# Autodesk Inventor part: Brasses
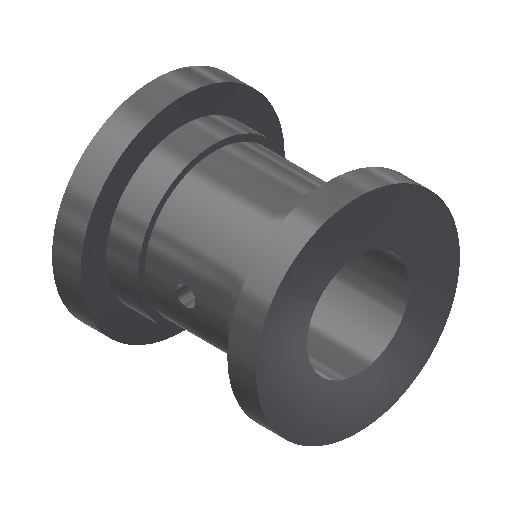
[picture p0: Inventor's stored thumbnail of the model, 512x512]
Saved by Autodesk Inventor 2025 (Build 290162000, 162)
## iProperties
Created: 2009-04
Part Number: Brasses
Document SubType Name: Modeling
Designer: Sham
Density: 7.85 g/cm^3
Material: Steel
Appearance: Smooth - Medium Gray
Author: Sham
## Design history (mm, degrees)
sketch "Sketch1"
  geometry: L1 (0, 32)-(9, 32); L2 (0, 16)-(64, 16); L3 (64, 32)-(55, 32); L4 (55, 32)-(55, 24); L5 (55, 24)-(47, 24); L6 (19, 22)-(47, 22); L7 (47, 24)-(47, 22); L8 (19, 22)-(19, 24); L9 (19, 24)-(9, 24); L10 (9, 24)-(9, 32); L11 (0, 32)-(0, 16); L12 (64, 32)-(64, 16); L13 (-12.8, 0)-(76.8, 0) reference; 1 further point
  constraints: 24 end point, 7 parallel, 4 perpendicular, 1 collinear, 1 horizontal, 1 vertical alignment, 1 other
  dimensions: "d0" = 9 distance of L1.start L1.end; "d2" = 16 distance from line of L2 point (0, 0); "d3" = 64 distance of L2.start L2.end; "d4" = 24 distance from line of point (0, 0) L5; "d5" = 28 distance of L6.start L6.end; "d6" = 22 distance from line of point (0, 0) L6; "d7" = 8 distance of L4.end L5.end; "d25" = 32 distance between parallel lines of L1 L13
revolve "Revolution2" sketch "Sketch1" stored, may be unused: angle "d16" = 90 deg
workplane "Work Plane2"
sketch "Sketch4"
  geometry: L1 (-32, 45.783)-(-32, -45.783); L2 (-64, 32)-(-64, -32) reference; L3 (0, 0)-(-64, 0); C1 r 4 at (-32, 0); 1 further point
  constraints: 4 end point, 2 midpoint, 1 centre point, 1 coincident, 1 horizontal, 1 vertical
  dimensions: "d18" = 32 distance between parallel lines of L1 L2; "d19" = 8 diameter of C1
extrude "Extrusion3" join sketch "Sketch4" stored distance "d20" = 0; taper "d21" = 0 deg
sketch "Sketch5"
  geometry: C1 r 3 at (0, 0); 1 further point
  constraints: 1 centre point
  dimensions: "d22" = 6 diameter of C1
extrude "Extrusion4" cut sketch "Sketch5" distance "d23" = 111; taper "d24" = 0 deg
body "Solid2"
